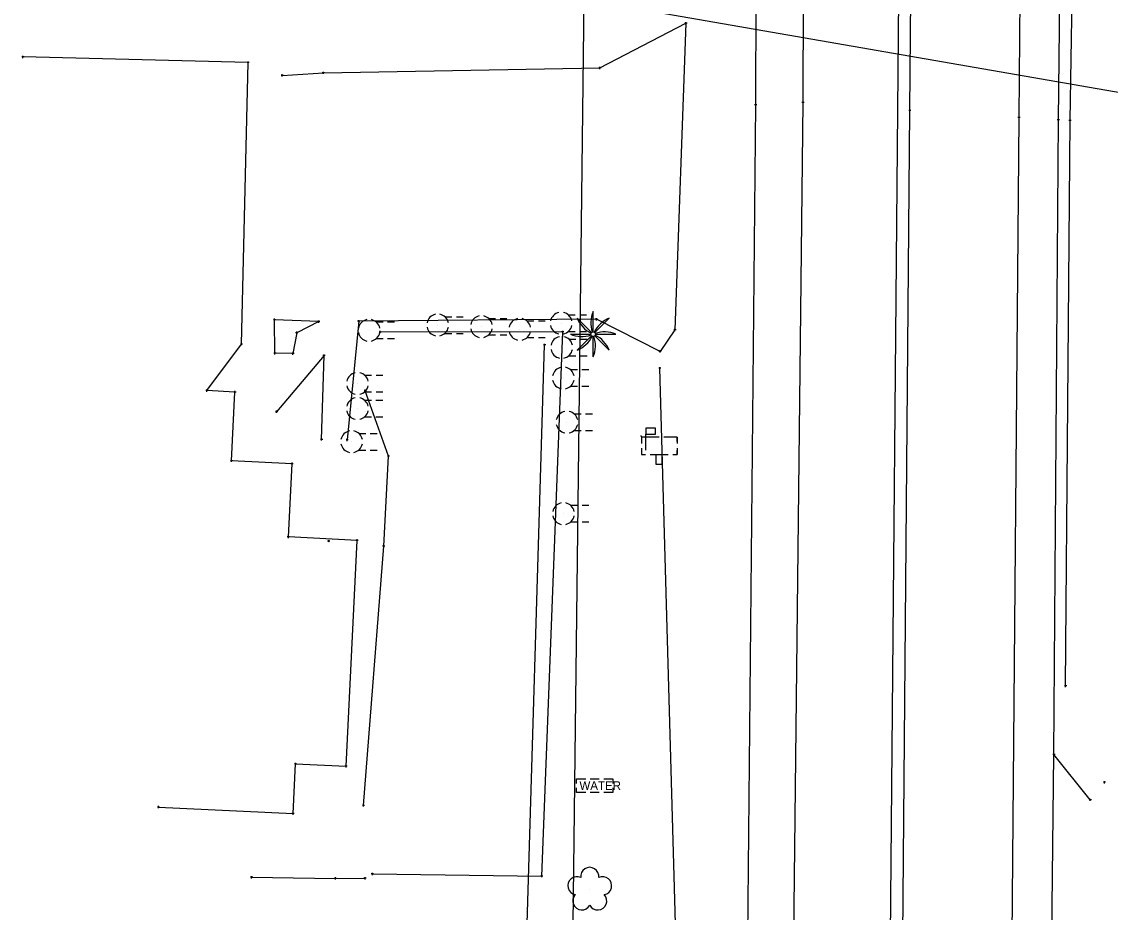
# Model space of a CAD drawing. Extents: x 1954856 to 2011933, y 399149 to 426294.
# Drawn here: x 2003850.6 to 2003971, y 411590.3 to 411688.7 of the extents above; entities that cross this region are included whole.
import ezdxf

# ---------------------------------------------------------------- set-up
doc = ezdxf.new("R2010")
doc.units = 0
for name, color, linetype in [('BankMent_ep', 7, 'Continuous'), ('BaselineSurvey', 7, 'Continuous'), ('Building_ep', 7, 'Continuous'), ('Driveway_ep', 7, 'Continuous'), ('ElecAer_ep', 7, 'Continuous'), ('Fence_ep', 7, 'Continuous'), ('FFElev_ep', 7, 'Continuous'), ('FloodLight_ep', 7, 'Continuous'), ('Gates_ep', 7, 'Continuous'), ('Mailbox_ep', 7, 'Continuous'), ('MeterWater_ep', 7, 'Continuous'), ('PavtAsphalt_ep', 7, 'Continuous'), ('PavtAsphaltCrown_ep', 7, 'Continuous'), ('PointLocator_ep', 7, 'Continuous'), ('ShldrPaved_ep', 7, 'Continuous'), ('ShrubHedge_ep', 7, 'Continuous'), ('SidewalkFront_ep', 7, 'Continuous'), ('Tree_ep', 7, 'Continuous'), ('TreePalm_ep', 7, 'Continuous')]:
    doc.layers.add(name, color=color, linetype=linetype)

msp = doc.modelspace()

# ---------------------------------------------------------------- linework, layer by layer
at = {"layer": 'BankMent_ep'}
for p, q in [((2003966.55, 411677.82), (2003968.2, 411778.81)), ((2003966.05, 411615.33), (2003966.55, 411677.82))]:
    msp.add_line(p, q, dxfattribs=at)
for points in [[(2003905.23, 411542.93), (2003906.25, 411580.45), (2003908.45, 411653.02)], [(2003927.48, 411549.48), (2003923.16, 411579.95), (2003921.19, 411650.43)]]:
    msp.add_lwpolyline(points, dxfattribs=at)
at = {"layer": 'BaselineSurvey'}
msp.add_line((2003939.73, 410808.61), (2003953.03, 412299.6), dxfattribs=at)
msp.add_line((2003939.73, 410808.61), (2003953.03, 412299.6), dxfattribs=at)
at = {"layer": 'Building_ep'}
msp.add_lwpolyline([(2003865.75, 411601.95), (2003880.64, 411601.23), (2003880.9, 411606.72), (2003886.5, 411606.45), (2003887.72, 411631.42), (2003880.13, 411631.8), (2003880.52, 411639.89), (2003873.83, 411640.21), (2003874.2, 411647.8), (2003871.1, 411647.96), (2003874.94, 411653.11), (2003875.67, 411684.22), (2003850.77, 411684.83)], dxfattribs=at)
at = {"layer": 'Driveway_ep'}
msp.add_line((2003968.78, 411602.75), (2003964.76, 411607.77), dxfattribs=at)
for points in [[(2003879.43, 411682.8), (2003883.99, 411683.08), (2003914.57, 411683.63), (2003924.07, 411688.55), (2003922.86, 411654.67), (2003921.21, 411652.29), (2003914.17, 411655.85), (2003887.89, 411655.63)], [(2003883.48, 411655.59), (2003878.59, 411655.79)]]:
    msp.add_lwpolyline(points, dxfattribs=at)
at = {"layer": 'ElecAer_ep'}
for points in [[(2003909.52, 411412.64), (2003912.81, 411691.22), (2003877.86, 411706.6)], [(2003912.81, 411691.22), (2003995.68, 411676.8), (2004074.67, 411677.07)]]:
    msp.add_lwpolyline(points, dxfattribs=at)
at = {"layer": 'Fence_ep'}
for points in [[(2003889.41, 411594.56), (2003908.14, 411594.33), (2003910.46, 411654.45), (2003890.26, 411654.44)], [(2003876.05, 411594.2), (2003885.33, 411594.07)]]:
    msp.add_lwpolyline(points, dxfattribs=at)
at = {"layer": 'FFElev_ep'}
for p, q in [((2003884.65, 411631.24), (2003884.47, 411631.42)), ((2003884.65, 411631.42), (2003884.47, 411631.24)), ((2003884.56, 411631.33), (2003884.56, 411631.33))]:
    msp.add_line(p, q, dxfattribs=at)
at = {"layer": 'FloodLight_ep'}
for p, q in [((2003897.42, 411656.13), (2003898.19, 411656.13)), ((2003898.69, 411656.13), (2003899.44, 411656.13)), ((2003911.06, 411656.34), (2003911.84, 411656.34)), ((2003912.34, 411656.34), (2003913.09, 411656.34)), ((2003889.82, 411655.55), (2003890.59, 411655.55)), ((2003891.09, 411655.55), (2003891.84, 411655.55)), ((2003896.63, 411655.21), (2003896.63, 411655.21)), ((2003901.46, 411655.03), (2003901.46, 411655.03)), ((2003902.25, 411655.95), (2003903.02, 411655.95)), ((2003903.52, 411655.95), (2003904.27, 411655.95)), ((2003906.49, 411655.66), (2003907.27, 411655.66)), ((2003907.77, 411655.66), (2003908.52, 411655.66)), ((2003910.28, 411655.41), (2003910.28, 411655.41)), ((2003889.04, 411654.63), (2003889.04, 411654.63)), ((2003889.82, 411653.71), (2003890.59, 411653.71)), ((2003891.09, 411653.71), (2003891.84, 411653.71)), ((2003897.42, 411654.29), (2003898.19, 411654.29)), ((2003898.69, 411654.29), (2003899.44, 411654.29)), ((2003902.25, 411654.11), (2003903.02, 411654.11)), ((2003903.52, 411654.11), (2003904.27, 411654.11)), ((2003905.71, 411654.74), (2003905.71, 411654.74)), ((2003906.49, 411653.82), (2003907.27, 411653.82)), ((2003907.77, 411653.82), (2003908.52, 411653.82)), ((2003911.06, 411654.5), (2003911.84, 411654.5)), ((2003911.13, 411653.66), (2003911.9, 411653.66)), ((2003912.34, 411654.5), (2003913.09, 411654.5)), ((2003912.4, 411653.66), (2003913.15, 411653.66)), ((2003910.34, 411652.74), (2003910.34, 411652.74)), ((2003911.13, 411651.82), (2003911.9, 411651.82)), ((2003912.4, 411651.82), (2003913.15, 411651.82)), ((2003911.3, 411650.28), (2003912.07, 411650.28)), ((2003912.57, 411650.28), (2003913.32, 411650.28)), ((2003888.55, 411649.67), (2003889.32, 411649.67)), ((2003889.82, 411649.67), (2003890.57, 411649.67)), ((2003910.52, 411649.36), (2003910.52, 411649.36)), ((2003887.76, 411648.75), (2003887.76, 411648.75)), ((2003888.55, 411647.83), (2003889.32, 411647.83)), ((2003889.82, 411647.83), (2003890.57, 411647.83)), ((2003911.3, 411648.44), (2003912.07, 411648.44)), ((2003912.57, 411648.44), (2003913.32, 411648.44)), ((2003888.53, 411646.9), (2003889.3, 411646.9)), ((2003889.8, 411646.9), (2003890.55, 411646.9)), ((2003887.75, 411645.98), (2003887.75, 411645.98)), ((2003911.71, 411645.4), (2003912.48, 411645.4)), ((2003912.98, 411645.4), (2003913.73, 411645.4)), ((2003888.53, 411645.06), (2003889.3, 411645.06)), ((2003889.8, 411645.06), (2003890.55, 411645.06)), ((2003910.92, 411644.48), (2003910.92, 411644.48)), ((2003887.9, 411643.24), (2003888.67, 411643.24)), ((2003889.17, 411643.24), (2003889.92, 411643.24)), ((2003911.71, 411643.56), (2003912.48, 411643.56)), ((2003912.98, 411643.56), (2003913.73, 411643.56)), ((2003887.11, 411642.32), (2003887.11, 411642.32)), ((2003887.9, 411641.4), (2003888.67, 411641.4)), ((2003889.17, 411641.4), (2003889.92, 411641.4)), ((2003910.53, 411634.37), (2003910.53, 411634.37)), ((2003911.32, 411635.29), (2003912.09, 411635.29)), ((2003912.59, 411635.29), (2003913.34, 411635.29)), ((2003911.32, 411633.45), (2003912.09, 411633.45)), ((2003912.59, 411633.45), (2003913.34, 411633.45))]:
    msp.add_line(p, q, dxfattribs=at)
for centre, start, end in [((2003896.63, 411655.21), 101.9232, 168.0768), ((2003896.63, 411655.21), 11.9232, 78.0768), ((2003901.46, 411655.03), 101.9232, 168.0768), ((2003901.46, 411655.03), 11.9232, 78.0768), ((2003910.28, 411655.41), 101.9232, 168.0768), ((2003910.28, 411655.41), 11.9232, 78.0768), ((2003889.04, 411654.63), 101.9232, 168.0768), ((2003889.04, 411654.63), 11.9232, 78.0768), ((2003896.63, 411655.21), 191.9232, 258.0768), ((2003896.63, 411655.21), 281.9232, 348.0768), ((2003901.46, 411655.03), 191.9232, 258.0768), ((2003901.46, 411655.03), 281.9232, 348.0768), ((2003905.71, 411654.74), 101.9232, 168.0768), ((2003905.71, 411654.74), 11.9232, 78.0768), ((2003910.28, 411655.41), 191.9232, 258.0768), ((2003910.28, 411655.41), 281.9232, 348.0768), ((2003889.04, 411654.63), 191.9232, 258.0768), ((2003889.04, 411654.63), 281.9232, 348.0768), ((2003905.71, 411654.74), 191.9232, 258.0768), ((2003905.71, 411654.74), 281.9232, 348.0768), ((2003910.34, 411652.74), 101.9232, 168.0768), ((2003910.34, 411652.74), 11.9232, 78.0768), ((2003910.34, 411652.74), 191.9232, 258.0768), ((2003910.34, 411652.74), 281.9232, 348.0768), ((2003910.52, 411649.36), 101.9232, 168.0768), ((2003910.52, 411649.36), 11.9232, 78.0768), ((2003887.76, 411648.75), 101.9232, 168.0768), ((2003887.76, 411648.75), 11.9232, 78.0768), ((2003910.52, 411649.36), 191.9232, 258.0768), ((2003910.52, 411649.36), 281.9232, 348.0768), ((2003887.76, 411648.75), 191.9232, 258.0768), ((2003887.76, 411648.75), 281.9232, 348.0768), ((2003887.75, 411645.98), 101.9232, 168.0768), ((2003887.75, 411645.98), 11.9232, 78.0768), ((2003887.75, 411645.98), 191.9232, 258.0768), ((2003887.75, 411645.98), 281.9232, 348.0768), ((2003910.92, 411644.48), 101.9232, 168.0768), ((2003910.92, 411644.48), 11.9232, 78.0768), ((2003910.92, 411644.48), 191.9232, 258.0768), ((2003910.92, 411644.48), 281.9232, 348.0768), ((2003887.11, 411642.32), 101.9232, 168.0768), ((2003887.11, 411642.32), 11.9232, 78.0768), ((2003887.11, 411642.32), 191.9232, 258.0768), ((2003887.11, 411642.32), 281.9232, 348.0768), ((2003910.53, 411634.37), 101.9232, 168.0768), ((2003910.53, 411634.37), 11.9232, 78.0768), ((2003910.53, 411634.37), 191.9232, 258.0768), ((2003910.53, 411634.37), 281.9232, 348.0768)]:
    msp.add_arc(centre, 1.21, start, end, dxfattribs=at)
at = {"layer": 'Gates_ep'}
msp.add_lwpolyline([(2003885.33, 411594.07), (2003888.59, 411594.09)], dxfattribs=at)
at = {"layer": 'Mailbox_ep'}
for p, q in [((2003919.16, 411642.82), (2003919.16, 411642.11)), ((2003921.11, 411642.82), (2003919.16, 411642.82)), ((2003919.62, 411641.4), (2003919.62, 411643.14)), ((2003919.62, 411643.14), (2003920.61, 411643.14)), ((2003923.11, 411642.82), (2003923.11, 411642.11)), ((2003923.11, 411641.61), (2003923.11, 411640.91)), ((2003920.11, 411640.91), (2003920.61, 411640.91)), ((2003920.61, 411640.91), (2003922.11, 411640.91)), ((2003921.09, 411639.83), (2003921.09, 411639.83))]:
    msp.add_line(p, q, dxfattribs=at)
for points in [[(2003919.05, 411642.95), (2003919.13, 411642.95), (2003919.16, 411642.77)], [(2003920.61, 411643.83), (2003919.62, 411643.83), (2003919.62, 411643.14)], [(2003920.61, 411643.14), (2003920.7, 411643.14), (2003920.7, 411643.83), (2003920.61, 411643.83)], [(2003923.11, 411642.36), (2003923.11, 411642.82), (2003921.61, 411642.82)], [(2003919.16, 411641.61), (2003919.16, 411640.91), (2003919.61, 411640.91)], [(2003920.75, 411640.91), (2003920.75, 411639.83), (2003921.44, 411639.83), (2003921.44, 411640.91)], [(2003922.61, 411640.91), (2003923.11, 411640.91), (2003923.11, 411641.36)]]:
    msp.add_lwpolyline(points, dxfattribs=at)
at = {"layer": 'MeterWater_ep'}
msp.add_line((2003913.99, 411604.32), (2003913.99, 411604.32), dxfattribs=at)
for points in [[(2003911.99, 411604.57), (2003911.99, 411605.07), (2003912.99, 411605.07)], [(2003913.49, 411605.07), (2003914.49, 411605.07)], [(2003914.99, 411605.07), (2003915.99, 411605.07), (2003915.99, 411604.57)], [(2003912.99, 411603.57), (2003911.99, 411603.57), (2003911.99, 411604.07)], [(2003914.49, 411603.57), (2003913.49, 411603.57)], [(2003915.99, 411604.07), (2003915.99, 411603.57), (2003914.99, 411603.57)]]:
    msp.add_lwpolyline(points, dxfattribs=at)
at = {"layer": 'PavtAsphalt_ep'}
for p, q in [((2003937.02, 411679.81), (2003937.53, 411779.26)), ((2003960.9, 411678.14), (2003961.75, 411778.65)), ((2003935.91, 411579.3), (2003937.02, 411679.81)), ((2003960.06, 411578.43), (2003960.9, 411678.14))]:
    msp.add_line(p, q, dxfattribs=at)
at = {"layer": 'PavtAsphaltCrown_ep'}
for p, q in [((2003948.83, 411678.92), (2003949.65, 411779.03)), ((2003947.97, 411578.87), (2003948.83, 411678.92))]:
    msp.add_line(p, q, dxfattribs=at)
at = {"layer": 'PointLocator_ep'}
for p, q in [((2003924.19, 411688.55), (2003923.94, 411688.55)), ((2003924.07, 411688.42), (2003924.07, 411688.67)), ((2003924.07, 411688.55), (2003924.07, 411688.55)), ((2003850.77, 411684.7), (2003850.77, 411684.95)), ((2003850.89, 411684.83), (2003850.64, 411684.83)), ((2003850.77, 411684.83), (2003850.77, 411684.83)), ((2003875.8, 411684.22), (2003875.55, 411684.22)), ((2003875.67, 411684.09), (2003875.67, 411684.34)), ((2003875.67, 411684.22), (2003875.67, 411684.22)), ((2003914.57, 411683.5), (2003914.57, 411683.75)), ((2003879.56, 411682.8), (2003879.31, 411682.8)), ((2003879.43, 411682.68), (2003879.43, 411682.93)), ((2003879.43, 411682.8), (2003879.43, 411682.8)), ((2003884.11, 411683.08), (2003883.86, 411683.08)), ((2003883.99, 411682.95), (2003883.99, 411683.2)), ((2003883.99, 411683.08), (2003883.99, 411683.08)), ((2003914.7, 411683.63), (2003914.45, 411683.63)), ((2003914.57, 411683.63), (2003914.57, 411683.63)), ((2003931.91, 411679.55), (2003931.66, 411679.55)), ((2003931.79, 411679.43), (2003931.79, 411679.68)), ((2003931.79, 411679.55), (2003931.79, 411679.55)), ((2003937.14, 411679.81), (2003936.89, 411679.81)), ((2003937.02, 411679.68), (2003937.02, 411679.93)), ((2003937.02, 411679.81), (2003937.02, 411679.81)), ((2003948.95, 411678.92), (2003948.7, 411678.92)), ((2003948.83, 411678.8), (2003948.83, 411679.05)), ((2003948.83, 411678.92), (2003948.83, 411678.92)), ((2003961.02, 411678.14), (2003960.77, 411678.14)), ((2003960.9, 411678.02), (2003960.9, 411678.27)), ((2003960.9, 411678.14), (2003960.9, 411678.14)), ((2003965.38, 411677.87), (2003965.13, 411677.87)), ((2003965.25, 411677.75), (2003965.25, 411678)), ((2003965.25, 411677.87), (2003965.25, 411677.87)), ((2003966.67, 411677.82), (2003966.42, 411677.82)), ((2003966.55, 411677.7), (2003966.55, 411677.95)), ((2003966.55, 411677.82), (2003966.55, 411677.82)), ((2003914.17, 411655.72), (2003914.17, 411655.97)), ((2003878.71, 411655.79), (2003878.46, 411655.79)), ((2003878.59, 411655.67), (2003878.59, 411655.92)), ((2003878.59, 411655.79), (2003878.59, 411655.79)), ((2003883.6, 411655.59), (2003883.35, 411655.59)), ((2003883.48, 411655.47), (2003883.48, 411655.72)), ((2003883.48, 411655.59), (2003883.48, 411655.59)), ((2003888.02, 411655.63), (2003887.77, 411655.63)), ((2003887.89, 411655.51), (2003887.89, 411655.76)), ((2003887.89, 411655.63), (2003887.89, 411655.63)), ((2003914.29, 411655.85), (2003914.04, 411655.85)), ((2003914.17, 411655.85), (2003914.17, 411655.85)), ((2003922.86, 411654.54), (2003922.86, 411654.79)), ((2003881.17, 411654.36), (2003880.92, 411654.36)), ((2003881.04, 411654.24), (2003881.04, 411654.49)), ((2003881.04, 411654.36), (2003881.04, 411654.36)), ((2003890.39, 411654.44), (2003890.14, 411654.44)), ((2003890.26, 411654.31), (2003890.26, 411654.56)), ((2003890.26, 411654.44), (2003890.26, 411654.44)), ((2003910.58, 411654.45), (2003910.33, 411654.45)), ((2003910.46, 411654.33), (2003910.46, 411654.58)), ((2003910.46, 411654.45), (2003910.46, 411654.45)), ((2003922.99, 411654.67), (2003922.74, 411654.67)), ((2003922.86, 411654.67), (2003922.86, 411654.67)), ((2003875.06, 411653.11), (2003874.81, 411653.11)), ((2003874.94, 411652.99), (2003874.94, 411653.24)), ((2003874.94, 411653.11), (2003874.94, 411653.11)), ((2003908.57, 411653.02), (2003908.32, 411653.02)), ((2003908.45, 411652.9), (2003908.45, 411653.15)), ((2003908.45, 411653.02), (2003908.45, 411653.02)), ((2003921.21, 411652.17), (2003921.21, 411652.42)), ((2003878.75, 411652.1), (2003878.5, 411652.1)), ((2003878.63, 411651.97), (2003878.63, 411652.22)), ((2003878.63, 411652.1), (2003878.63, 411652.1)), ((2003880.75, 411652.05), (2003880.5, 411652.05)), ((2003880.62, 411651.93), (2003880.62, 411652.18)), ((2003880.62, 411652.05), (2003880.62, 411652.05)), ((2003884.19, 411651.83), (2003883.94, 411651.83)), ((2003884.06, 411651.7), (2003884.06, 411651.95)), ((2003884.06, 411651.83), (2003884.06, 411651.83)), ((2003921.33, 411652.29), (2003921.08, 411652.29)), ((2003921.21, 411652.29), (2003921.21, 411652.29)), ((2003921.31, 411650.43), (2003921.06, 411650.43)), ((2003921.19, 411650.31), (2003921.19, 411650.56)), ((2003921.19, 411650.43), (2003921.19, 411650.43)), ((2003871.23, 411647.96), (2003870.98, 411647.96)), ((2003871.1, 411647.83), (2003871.1, 411648.08)), ((2003871.1, 411647.96), (2003871.1, 411647.96)), ((2003874.33, 411647.8), (2003874.08, 411647.8)), ((2003874.2, 411647.68), (2003874.2, 411647.93)), ((2003874.2, 411647.8), (2003874.2, 411647.8)), ((2003888.74, 411647.95), (2003888.49, 411647.95)), ((2003888.61, 411647.83), (2003888.61, 411648.08)), ((2003888.61, 411647.95), (2003888.61, 411647.95)), ((2003878.94, 411645.63), (2003878.69, 411645.63)), ((2003878.81, 411645.51), (2003878.81, 411645.76)), ((2003878.81, 411645.63), (2003878.81, 411645.63)), ((2003883.92, 411642.56), (2003883.67, 411642.56)), ((2003883.79, 411642.44), (2003883.79, 411642.69)), ((2003883.79, 411642.56), (2003883.79, 411642.56)), ((2003886.74, 411642.51), (2003886.49, 411642.51)), ((2003886.61, 411642.38), (2003886.61, 411642.63)), ((2003886.61, 411642.51), (2003886.61, 411642.51)), ((2003873.83, 411640.09), (2003873.83, 411640.34)), ((2003891.31, 411640.72), (2003891.06, 411640.72)), ((2003891.18, 411640.6), (2003891.18, 411640.85)), ((2003891.18, 411640.72), (2003891.18, 411640.72)), ((2003873.96, 411640.21), (2003873.71, 411640.21)), ((2003873.83, 411640.21), (2003873.83, 411640.21)), ((2003880.65, 411639.89), (2003880.4, 411639.89)), ((2003880.52, 411639.76), (2003880.52, 411640.01)), ((2003880.52, 411639.89), (2003880.52, 411639.89)), ((2003880.13, 411631.67), (2003880.13, 411631.92)), ((2003880.25, 411631.8), (2003880, 411631.8)), ((2003880.13, 411631.8), (2003880.13, 411631.8)), ((2003887.84, 411631.42), (2003887.59, 411631.42)), ((2003887.72, 411631.3), (2003887.72, 411631.55)), ((2003887.72, 411631.42), (2003887.72, 411631.42)), ((2003890.79, 411630.76), (2003890.54, 411630.76)), ((2003890.67, 411630.63), (2003890.67, 411630.88)), ((2003890.67, 411630.76), (2003890.67, 411630.76)), ((2003966.17, 411615.33), (2003965.92, 411615.33)), ((2003966.05, 411615.2), (2003966.05, 411615.45)), ((2003966.05, 411615.33), (2003966.05, 411615.33)), ((2003964.76, 411607.65), (2003964.76, 411607.9)), ((2003881.03, 411606.72), (2003880.78, 411606.72)), ((2003880.9, 411606.6), (2003880.9, 411606.85)), ((2003880.9, 411606.72), (2003880.9, 411606.72)), ((2003964.89, 411607.77), (2003964.64, 411607.77)), ((2003964.76, 411607.77), (2003964.76, 411607.77)), ((2003886.62, 411606.45), (2003886.37, 411606.45)), ((2003886.5, 411606.32), (2003886.5, 411606.57)), ((2003886.5, 411606.45), (2003886.5, 411606.45)), ((2003970.47, 411604.69), (2003970.22, 411604.69)), ((2003970.34, 411604.57), (2003970.34, 411604.82)), ((2003970.34, 411604.69), (2003970.34, 411604.69)), ((2003865.88, 411601.95), (2003865.63, 411601.95)), ((2003865.75, 411601.83), (2003865.75, 411602.08)), ((2003865.75, 411601.95), (2003865.75, 411601.95)), ((2003888.55, 411602.13), (2003888.3, 411602.13)), ((2003888.43, 411602), (2003888.43, 411602.25)), ((2003888.43, 411602.13), (2003888.43, 411602.13)), ((2003968.9, 411602.75), (2003968.65, 411602.75)), ((2003968.78, 411602.62), (2003968.78, 411602.87)), ((2003968.78, 411602.75), (2003968.78, 411602.75)), ((2003880.76, 411601.23), (2003880.51, 411601.23)), ((2003880.64, 411601.1), (2003880.64, 411601.35)), ((2003880.64, 411601.23), (2003880.64, 411601.23)), ((2003889.41, 411594.44), (2003889.41, 411594.69)), ((2003876.17, 411594.2), (2003875.92, 411594.2)), ((2003876.05, 411594.07), (2003876.05, 411594.32)), ((2003876.05, 411594.2), (2003876.05, 411594.2)), ((2003885.45, 411594.07), (2003885.2, 411594.07)), ((2003885.33, 411593.94), (2003885.33, 411594.19)), ((2003885.33, 411594.07), (2003885.33, 411594.07)), ((2003888.72, 411594.09), (2003888.47, 411594.09)), ((2003888.59, 411593.96), (2003888.59, 411594.21)), ((2003888.59, 411594.09), (2003888.59, 411594.09)), ((2003889.53, 411594.56), (2003889.28, 411594.56)), ((2003889.41, 411594.56), (2003889.41, 411594.56)), ((2003908.26, 411594.33), (2003908.01, 411594.33)), ((2003908.14, 411594.21), (2003908.14, 411594.46)), ((2003908.14, 411594.33), (2003908.14, 411594.33))]:
    msp.add_line(p, q, dxfattribs=at)
at = {"layer": 'ShldrPaved_ep'}
for p, q in [((2003965.25, 411677.87), (2003966.33, 411778.79)), ((2003931.79, 411679.55), (2003931.99, 411724.09)), ((2003930.84, 411579.44), (2003931.79, 411679.55)), ((2003964.76, 411607.77), (2003965.25, 411677.87)), ((2003964.4, 411578.36), (2003964.76, 411607.77))]:
    msp.add_line(p, q, dxfattribs=at)
at = {"layer": 'ShrubHedge_ep'}
for points in [[(2003890.67, 411630.76), (2003891.18, 411640.72), (2003888.61, 411647.95)], [(2003888.43, 411602.13), (2003890.67, 411630.76)]]:
    msp.add_lwpolyline(points, dxfattribs=at)
at = {"layer": 'SidewalkFront_ep'}
for points in [[(2003883.48, 411655.59), (2003881.04, 411654.36), (2003880.62, 411652.05), (2003878.63, 411652.1), (2003878.59, 411655.79)], [(2003887.89, 411655.63), (2003886.61, 411642.51)], [(2003883.79, 411642.56), (2003884.06, 411651.83), (2003878.81, 411645.63)]]:
    msp.add_lwpolyline(points, dxfattribs=at)
at = {"layer": 'Tree_ep'}
msp.add_line((2003913.44, 411592.79), (2003913.44, 411592.79), dxfattribs=at)
for centre, start, end in [((2003913.44, 411594.29), 352.1546, 187.8454), ((2003912.01, 411593.26), 64.1546, 259.8454), ((2003914.86, 411593.26), 280.1546, 115.8454), ((2003912.56, 411591.58), 136.1546, 331.8454), ((2003914.32, 411591.58), 208.1546, 43.8454)]:
    msp.add_arc(centre, 1, start, end, dxfattribs=at)
at = {"layer": 'TreePalm_ep'}
for p, q in [((2003913.64, 411654.38), (2003912.05, 411655.97)), ((2003913.81, 411654.45), (2003913.81, 411656.7)), ((2003913.99, 411654.38), (2003915.58, 411655.97)), ((2003911.31, 411654.2), (2003913.56, 411654.2)), ((2003912.05, 411652.43), (2003913.64, 411654.03)), ((2003913.81, 411654.2), (2003913.81, 411654.2)), ((2003913.81, 411651.7), (2003913.81, 411653.95)), ((2003915.58, 411652.43), (2003913.99, 411654.03)), ((2003914.06, 411654.2), (2003916.31, 411654.2))]:
    msp.add_line(p, q, dxfattribs=at)
msp.add_circle((2003913.81, 411654.2), 0.25, dxfattribs=at)
for centre, start, end in [((2003915.05, 411657.21), 202.3801, 243.2114), ((2003916.81, 411655.45), 157.3801, 198.2114), ((2003916.82, 411652.96), 112.3801, 153.2114), ((2003912.56, 411657.2), 247.3801, 288.2114), ((2003910.81, 411655.44), 292.3801, 333.2114), ((2003910.81, 411652.95), 337.3801, 18.2114), ((2003912.58, 411651.2), 22.3801, 63.2114), ((2003915.06, 411651.2), 67.3801, 108.2114)]:
    msp.add_arc(centre, 3.25, start, end, dxfattribs=at)

# ---------------------------------------------------------------- texts
at = {"layer": 'MeterWater_ep'}
msp.add_text('WATER', height=0.95, dxfattribs=at).set_placement((2003912.3, 411603.85))

doc.saveas('drawing.dxf')
